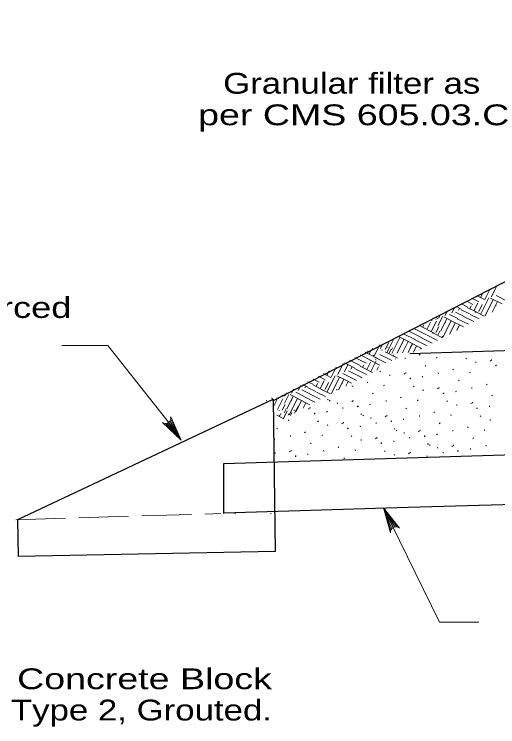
# Model space of a CAD drawing. Extents: x 1083.1 to 1117.1, y 697.4 to 741.4.
# Drawn here: x 1090.18 to 1093.81, y 702.44 to 707.78 of the extents above; entities that cross this region are included whole.
import ezdxf
from ezdxf.enums import TextEntityAlignment as Align

# ---------------------------------------------------------------- set-up
doc = ezdxf.new("R2010")
doc.units = 0
doc.header["$LTSCALE"] = 0.062
doc.linetypes.add('LONG_DASHED', pattern=[7.5, 6, -1.5])
doc.layers.add('1', color=7, linetype='Continuous', lineweight=13)

msp = doc.modelspace()

# ---------------------------------------------------------------- linework, layer by layer
at = {"layer": '1', "lineweight": 25}
for p, q in [((1097.77125, 707.78017), (1092.11942, 704.88033)), ((1098.91383, 705.41058), (1093.14742, 705.23408)), ((1093.22625, 705.22533), (1093.22142, 705.23075)), ((1093.34717, 705.20683), (1093.35225, 705.20767)), ((1093.11025, 705.20142), (1093.1155, 705.20233)), ((1093.57275, 705.19608), (1093.56792, 705.2015)), ((1093.64, 705.17108), (1093.64517, 705.17208)), ((1093.75433, 705.17942), (1093.7495, 705.18467)), ((1093.75867, 705.18908), (1093.76383, 705.19008)), ((1092.92925, 705.09867), (1092.92442, 705.10408)), ((1093.26708, 705.14225), (1093.26225, 705.14758)), ((1093.47667, 705.11383), (1093.47183, 705.11925)), ((1093.79117, 705.14617), (1093.79633, 705.147)), ((1093.79383, 705.14817), (1093.799, 705.149)), ((1092.9965, 705.07367), (1093.00167, 705.07467)), ((1093.11083, 705.082), (1093.106, 705.08733)), ((1093.11517, 705.09167), (1093.12033, 705.09267)), ((1093.14767, 705.04883), (1093.15283, 705.04967)), ((1093.15033, 705.05075), (1093.15558, 705.05158)), ((1093.24158, 705.064), (1093.24683, 705.06483)), ((1093.36067, 705.08992), (1093.36592, 705.09083)), ((1093.59758, 705.09533), (1093.60275, 705.09617)), ((1092.71717, 704.9925), (1092.72242, 704.9935)), ((1092.83317, 705.0165), (1092.82833, 705.02192)), ((1092.95408, 704.99792), (1092.95925, 704.99883)), ((1093.17967, 704.98717), (1093.17483, 704.99258)), ((1093.5175, 705.03075), (1093.51267, 705.03608)), ((1093.72708, 705.00233), (1093.72225, 705.00775)), ((1092.59808, 704.96658), (1092.60333, 704.96742)), ((1092.874, 704.93342), (1092.86917, 704.93875)), ((1093.24692, 704.96217), (1093.25208, 704.96317)), ((1093.36133, 704.9705), (1093.35642, 704.97583)), ((1093.36558, 704.98017), (1093.37075, 704.98117)), ((1093.39808, 704.93733), (1093.40333, 704.93817)), ((1093.40075, 704.93925), (1093.406, 704.94008)), ((1093.492, 704.9525), (1093.49725, 704.95333)), ((1093.61108, 704.97842), (1093.61633, 704.97933)), ((1092.53617, 704.88983), (1092.53133, 704.89525)), ((1092.55033, 704.88033), (1092.5455, 704.88567)), ((1093.08358, 704.905), (1093.07883, 704.91042)), ((1093.2045, 704.88642), (1093.20967, 704.88733)), ((1093.76792, 704.91933), (1093.76308, 704.92458)), ((1092.39842, 704.82975), (1092.40358, 704.83075)), ((1092.60342, 704.86483), (1092.60858, 704.86583)), ((1092.71783, 704.87317), (1092.713, 704.87842)), ((1092.72217, 704.88283), (1092.72733, 704.88375)), ((1092.75458, 704.83992), (1092.75983, 704.84075)), ((1092.75725, 704.84192), (1092.7625, 704.84275)), ((1092.8485, 704.85508), (1092.85375, 704.85592)), ((1092.96758, 704.881), (1092.97283, 704.882)), ((1093.43008, 704.87567), (1093.42525, 704.88108)), ((1093.49733, 704.85067), (1093.5025, 704.85167)), ((1093.61175, 704.859), (1093.60683, 704.86433)), ((1093.616, 704.86875), (1093.62125, 704.86967)), ((1093.74242, 704.841), (1093.74767, 704.84183)), ((1092.27975, 704.81175), (1092.28492, 704.81275)), ((1092.39408, 704.82008), (1092.38925, 704.82542)), ((1092.43092, 704.78683), (1092.43608, 704.78767)), ((1092.43358, 704.78883), (1092.43883, 704.78967)), ((1092.52483, 704.802), (1092.53008, 704.80283)), ((1092.64392, 704.828), (1092.64917, 704.82892)), ((1092.78658, 704.77833), (1092.78175, 704.78375)), ((1093.1245, 704.82192), (1093.11958, 704.82725)), ((1093.334, 704.7935), (1093.32925, 704.79892)), ((1093.6485, 704.82583), (1093.65375, 704.82667)), ((1093.65117, 704.82783), (1093.65642, 704.82867)), ((1092.23733, 704.736), (1092.2425, 704.73683)), ((1092.46292, 704.72525), (1092.45808, 704.73067)), ((1092.80075, 704.76883), (1092.79592, 704.77417)), ((1092.85383, 704.75333), (1092.85908, 704.75433)), ((1092.96825, 704.76167), (1092.96342, 704.76692)), ((1092.97258, 704.77133), (1092.97775, 704.77233)), ((1093.005, 704.72842), (1093.01025, 704.72925)), ((1093.00767, 704.73042), (1093.01292, 704.73125)), ((1093.099, 704.74358), (1093.10417, 704.74442)), ((1093.218, 704.76958), (1093.22325, 704.7705)), ((1093.45492, 704.77492), (1093.46008, 704.77583)), ((1093.6805, 704.76417), (1093.67567, 704.76958)), ((1093.74775, 704.73925), (1093.75292, 704.74017)), ((1092.15725, 704.6715), (1092.15242, 704.67675)), ((1092.53017, 704.70025), (1092.53533, 704.70125)), ((1092.6445, 704.70858), (1092.63967, 704.71392)), ((1092.64883, 704.71825), (1092.654, 704.71925)), ((1092.68133, 704.67542), (1092.68658, 704.67625)), ((1092.684, 704.67733), (1092.68925, 704.67817)), ((1092.77525, 704.6905), (1092.7805, 704.69133)), ((1092.89433, 704.7165), (1092.89958, 704.71742)), ((1093.037, 704.66683), (1093.03225, 704.67225)), ((1093.37492, 704.71042), (1093.37, 704.71575)), ((1093.58442, 704.682), (1093.57967, 704.68742)), ((1091.7535, 704.41092), (1098.91383, 704.63642)), ((1092.25083, 704.61908), (1092.25608, 704.62)), ((1092.36683, 704.643), (1092.362, 704.64842)), ((1092.48775, 704.6245), (1092.49292, 704.62533)), ((1092.71333, 704.61375), (1092.7085, 704.61917)), ((1093.05117, 704.65733), (1093.04633, 704.66267)), ((1093.10433, 704.64183), (1093.1095, 704.64283)), ((1093.21867, 704.65017), (1093.21383, 704.65542)), ((1093.223, 704.65983), (1093.22817, 704.66083)), ((1093.25542, 704.61692), (1093.26067, 704.61775)), ((1093.25808, 704.61892), (1093.26333, 704.61975)), ((1093.34942, 704.63208), (1093.35458, 704.63292)), ((1093.46842, 704.65808), (1093.47367, 704.659)), ((1093.70533, 704.66342), (1093.7105, 704.66433)), ((1092.13175, 704.59317), (1092.137, 704.594)), ((1092.40775, 704.56), (1092.40283, 704.56533)), ((1092.78058, 704.58875), (1092.78575, 704.58975)), ((1092.895, 704.59708), (1092.89008, 704.60242)), ((1092.89925, 704.60675), (1092.90442, 704.60775)), ((1092.93175, 704.56392), (1092.937, 704.56475)), ((1092.93442, 704.56583), (1092.93967, 704.56667)), ((1093.02567, 704.579), (1093.03092, 704.57983)), ((1093.14475, 704.605), (1093.15, 704.60592)), ((1093.62533, 704.59892), (1093.62042, 704.60425)), ((1092.25583, 704.50942), (1092.261, 704.51033)), ((1092.61725, 704.5315), (1092.6125, 704.53692)), ((1092.73817, 704.513), (1092.74333, 704.51392)), ((1093.28742, 704.55533), (1093.28267, 704.56075)), ((1093.30158, 704.54583), (1093.29675, 704.55117)), ((1093.35475, 704.53033), (1093.35992, 704.53133)), ((1093.46908, 704.53867), (1093.46425, 704.54392)), ((1093.47342, 704.54833), (1093.47858, 704.54933)), ((1093.59975, 704.52058), (1093.605, 704.52142)), ((1093.71883, 704.54658), (1093.72408, 704.5475)), ((1092.13717, 704.49142), (1092.14225, 704.49233)), ((1092.2515, 704.49967), (1092.24667, 704.505)), ((1092.28825, 704.4665), (1092.2935, 704.46733)), ((1092.29092, 704.4685), (1092.29617, 704.46933)), ((1092.38217, 704.48167), (1092.38742, 704.4825)), ((1092.50125, 704.50758), (1092.5065, 704.5085)), ((1092.96375, 704.50225), (1092.95892, 704.50767)), ((1093.031, 704.47725), (1093.03617, 704.47825)), ((1093.14542, 704.48558), (1093.1405, 704.49092)), ((1093.14967, 704.49525), (1093.15492, 704.49625)), ((1093.27608, 704.4675), (1093.28133, 704.46833)), ((1093.39517, 704.4935), (1093.40042, 704.49442)), ((1093.50583, 704.5055), (1093.51108, 704.50633)), ((1093.5085, 704.50742), (1093.51375, 704.50825)), ((1091.7535, 704.03733), (1091.7535, 704.41092)), ((1092.65817, 704.4485), (1092.65325, 704.45383)), ((1093.13575, 704.08392), (1100.04408, 704.29175)), ((1091.7535, 704.04233), (1093.13575, 704.08392)), ((1091.83925, 704.0335), (1091.8415, 704.0385)), ((1092.107, 704.0335), (1092.10917, 704.0385))]:
    msp.add_line(p, q, dxfattribs=at)
at = {"layer": '1'}
for p, q in [((1093.78875, 705.71933), (1093.801, 705.74383)), ((1093.678, 705.65592), (1093.69467, 705.68925)), ((1093.71, 705.64083), (1093.74783, 705.71658)), ((1093.7595, 705.66083), (1093.78808, 705.71808)), ((1093.6145, 705.64808), (1093.66525, 705.62275)), ((1093.65358, 705.66808), (1093.709, 705.64042)), ((1093.6785, 705.52958), (1093.73992, 705.65292)), ((1093.713, 705.5195), (1093.77358, 705.64092)), ((1093.753, 705.65267), (1093.83925, 705.60975)), ((1093.79667, 705.67042), (1093.88808, 705.62475)), ((1093.46242, 705.54083), (1093.48192, 705.57992)), ((1093.49725, 705.58775), (1093.53367, 705.56958)), ((1093.53625, 705.60783), (1093.5775, 705.58733)), ((1093.57533, 705.62792), (1093.62133, 705.605)), ((1093.57775, 705.58183), (1093.65058, 705.5455)), ((1093.59683, 705.57233), (1093.60758, 705.59392)), ((1093.6285, 705.5565), (1093.65708, 705.61392)), ((1093.665, 705.55033), (1093.69117, 705.60275)), ((1093.76617, 705.54692), (1093.80533, 705.62533)), ((1093.79117, 705.59367), (1093.79467, 705.60075)), ((1093.36325, 705.50075), (1093.3755, 705.52525)), ((1093.41292, 705.52083), (1093.42425, 705.54342)), ((1093.42483, 705.54475), (1093.42883, 705.55267)), ((1093.44633, 705.52867), (1093.50792, 705.49792)), ((1093.49008, 705.54642), (1093.5555, 705.51375)), ((1093.512, 705.56083), (1093.51983, 705.57658)), ((1093.534, 705.56417), (1093.59492, 705.53367)), ((1093.59933, 705.5295), (1093.667, 705.49583)), ((1093.63758, 705.54833), (1093.6445, 705.54483)), ((1093.64683, 705.54542), (1093.706, 705.51592)), ((1093.68517, 705.56417), (1093.68567, 705.56392)), ((1093.30225, 705.48758), (1093.315, 705.48125)), ((1093.30742, 705.4005), (1093.34717, 705.48008)), ((1093.341, 705.5075), (1093.35842, 705.49883)), ((1093.34275, 705.491), (1093.34367, 705.49283)), ((1093.3605, 705.44708), (1093.39333, 705.51292)), ((1093.37817, 705.40333), (1093.425, 705.49717)), ((1093.39583, 705.35958), (1093.45692, 705.48183)), ((1093.40258, 705.511), (1093.45942, 705.48267)), ((1093.41133, 705.46658), (1093.41508, 705.474)), ((1093.45692, 705.48183), (1093.54992, 705.4355)), ((1093.50433, 705.49775), (1093.58892, 705.45558)), ((1093.55175, 705.51358), (1093.62792, 705.47567)), ((1093.18358, 705.42275), (1093.27392, 705.37767)), ((1093.224, 705.44742), (1093.22725, 705.44583)), ((1093.22742, 705.4405), (1093.32992, 705.38925)), ((1093.24408, 705.432), (1093.25358, 705.45108)), ((1093.26308, 705.4675), (1093.27108, 705.4635)), ((1093.27575, 705.41625), (1093.30317, 705.47108)), ((1093.34383, 705.39392), (1093.36492, 705.43617)), ((1093.44667, 705.38225), (1093.47208, 705.43317)), ((1093.47275, 705.43442), (1093.4885, 705.46608)), ((1093.50008, 705.40975), (1093.52025, 705.45033)), ((1093.1015, 705.38442), (1093.18733, 705.34167)), ((1093.14058, 705.4045), (1093.23483, 705.3575)), ((1093.27833, 705.37342), (1093.35517, 705.33517)), ((1093.31692, 705.39208), (1093.3235, 705.38883)), ((1093.32583, 705.38933), (1093.39417, 705.35525)), ((1093.35742, 705.3735), (1093.37325, 705.40517)), ((1093.3645, 705.40792), (1093.36467, 705.40792)), ((1093.38908, 705.35775), (1093.39325, 705.366)), ((1092.96425, 705.26717), (1092.99033, 705.31958)), ((1092.97767, 705.2465), (1093.0275, 705.34642)), ((1093.01233, 705.23675), (1093.07283, 705.35775)), ((1093.05317, 705.23925), (1093.1045, 705.34217)), ((1093.0625, 705.36442), (1093.13842, 705.32658)), ((1093.09033, 705.31058), (1093.09383, 705.31758)), ((1093.09392, 705.24175), (1093.13583, 705.32575)), ((1093.13583, 705.32575), (1093.23808, 705.27475)), ((1093.18333, 705.34167), (1093.27708, 705.29492)), ((1093.23075, 705.3575), (1093.31608, 705.315)), ((1092.843, 705.23192), (1092.85875, 705.26358)), ((1092.86367, 705.26167), (1092.87008, 705.27458)), ((1092.88142, 705.21792), (1092.92325, 705.30192)), ((1092.92767, 705.27342), (1092.94225, 705.30258)), ((1092.93675, 705.26517), (1092.94367, 705.26175)), ((1092.98433, 705.281), (1092.98483, 705.28083)), ((1092.99117, 705.23525), (1093.00692, 705.26692)), ((1093.01183, 705.265), (1093.01825, 705.27792)), ((1093.13467, 705.24425), (1093.15108, 705.27708)), ((1093.15175, 705.27833), (1093.1675, 705.31)), ((1093.17558, 705.24675), (1093.19925, 705.29425)), ((1093.226, 705.2685), (1093.23092, 705.27842)), ((1092.73642, 705.20583), (1092.82042, 705.164)), ((1092.77558, 705.226), (1092.86433, 705.18175)), ((1092.81458, 705.24608), (1092.884, 705.21142)), ((1092.82933, 705.25225), (1092.83025, 705.25408)), ((1092.87467, 705.21608), (1092.87875, 705.22442)), ((1092.88417, 705.211), (1092.90775, 705.19925)), ((1092.88458, 705.20917), (1092.96858, 705.16733)), ((1092.92375, 705.22933), (1093.0125, 705.18508)), ((1092.96275, 705.24942), (1093.03217, 705.21475)), ((1092.9775, 705.25558), (1092.97842, 705.25742)), ((1093.02283, 705.21942), (1093.02692, 705.22775)), ((1093.03233, 705.21433), (1093.05592, 705.20258)), ((1092.63725, 705.13667), (1092.6495, 705.16117)), ((1092.65767, 705.09825), (1092.68475, 705.15258)), ((1092.65825, 705.16575), (1092.73275, 705.12858)), ((1092.69733, 705.18575), (1092.77658, 705.14625)), ((1092.79342, 705.1325), (1092.80292, 705.1515)), ((1092.82508, 705.11675), (1092.85242, 705.17158)), ((1092.8455, 705.18908), (1092.92475, 705.14958)), ((1092.85675, 705.10092), (1092.8965, 705.18058)), ((1092.89208, 705.19142), (1092.893, 705.19333)), ((1093.04025, 705.19475), (1093.04117, 705.19667)), ((1092.5265, 705.07325), (1092.54317, 705.10658)), ((1092.5585, 705.05817), (1092.59633, 705.13392)), ((1092.608, 705.07817), (1092.63658, 705.13542)), ((1092.689, 705.1055), (1092.78417, 705.058)), ((1092.70717, 705.11825), (1092.71642, 705.13675)), ((1092.73292, 705.12325), (1092.82325, 705.07808)), ((1092.77667, 705.14092), (1092.86858, 705.09508)), ((1092.90208, 705.11242), (1092.91425, 705.13667)), ((1092.42383, 705.04525), (1092.46983, 705.02233)), ((1092.463, 705.06542), (1092.51375, 705.04008)), ((1092.50208, 705.08542), (1092.5575, 705.05775)), ((1092.527, 704.94692), (1092.58842, 705.07025)), ((1092.5615, 704.93683), (1092.62208, 705.05825)), ((1092.6015, 705.07), (1092.68775, 705.02708)), ((1092.64517, 705.08775), (1092.73658, 705.04208)), ((1092.78008, 705.058), (1092.7885, 705.05383)), ((1092.31092, 704.95817), (1092.33042, 704.99725)), ((1092.34575, 705.00508), (1092.38217, 704.98692)), ((1092.3605, 704.97817), (1092.36833, 704.99392)), ((1092.38475, 705.02517), (1092.426, 705.00467)), ((1092.42625, 704.99917), (1092.49908, 704.96283)), ((1092.44533, 704.98967), (1092.45608, 705.01125)), ((1092.477, 704.97383), (1092.50558, 705.03125)), ((1092.5135, 704.96767), (1092.53967, 705.02008)), ((1092.61467, 704.96425), (1092.65383, 705.04267)), ((1092.63967, 705.011), (1092.64317, 705.01808)), ((1092.66792, 704.99167), (1092.68517, 705.02625)), ((1092.68517, 705.02625), (1092.7105, 705.01367)), ((1092.73258, 705.04217), (1092.7495, 705.03375)), ((1092.21175, 704.91808), (1092.224, 704.94258)), ((1092.26142, 704.93817), (1092.27275, 704.96075)), ((1092.27333, 704.96208), (1092.27733, 704.97)), ((1092.29483, 704.946), (1092.35642, 704.91525)), ((1092.33858, 704.96375), (1092.404, 704.93108)), ((1092.3825, 704.9815), (1092.44342, 704.951)), ((1092.44783, 704.94683), (1092.5155, 704.91317)), ((1092.48608, 704.96567), (1092.493, 704.96217)), ((1092.49533, 704.96275), (1092.5545, 704.93325)), ((1092.53367, 704.9815), (1092.53417, 704.98125)), ((1092.11158, 704.90358), (1092.11958, 704.89958)), ((1092.12425, 704.83358), (1092.15167, 704.88842)), ((1092.15075, 704.90492), (1092.1635, 704.89858)), ((1092.15592, 704.81783), (1092.19567, 704.89742)), ((1092.1895, 704.92483), (1092.20692, 704.91617)), ((1092.19125, 704.90833), (1092.19217, 704.91017)), ((1092.209, 704.86442), (1092.24183, 704.93025)), ((1092.22667, 704.82067), (1092.2735, 704.9145)), ((1092.24433, 704.77692), (1092.30542, 704.89917)), ((1092.25108, 704.92833), (1092.30792, 704.9)), ((1092.25983, 704.88392), (1092.26358, 704.89133)), ((1092.30542, 704.89917), (1092.39842, 704.85283)), ((1092.35283, 704.91508), (1092.43742, 704.87292)), ((1092.40025, 704.93092), (1092.47642, 704.893)), ((1092.0725, 704.8835), (1092.07575, 704.88192)), ((1092.19233, 704.81125), (1092.21342, 704.8535)), ((1092.28508, 704.789), (1092.31292, 704.84483)), ((1092.29517, 704.79958), (1092.32058, 704.8505)), ((1092.32125, 704.85175), (1092.337, 704.88342)), ((1092.34858, 704.82708), (1092.36875, 704.86767)), ((1092.16542, 704.80942), (1092.172, 704.80617)), ((1092.16975, 704.76425), (1092.18058, 704.78583)), ((1092.20142, 704.74842), (1092.23, 704.80575)), ((1092.20592, 704.79083), (1092.22175, 704.8225)), ((1092.213, 704.82525), (1092.21317, 704.82525)), ((1092.23758, 704.77508), (1092.24175, 704.78333)), ((1092.25308, 704.7725), (1092.26417, 704.79458)), ((1091.35067, 704.73117), (1091.43492, 704.58683)), ((1091.35592, 704.74292), (1091.43492, 704.58683)), ((1092.15075, 704.77375), (1092.204, 704.74717)), ((1091.31608, 704.712), (1091.43492, 704.58683)), ((1091.32908, 704.71417), (1091.43492, 704.58683)), ((1091.33992, 704.71975), (1091.43492, 704.58683)), ((1093.02508, 703.933), (1092.95058, 704.07833)), ((1093.01275, 703.92325), (1092.95058, 704.07833)), ((1093.00583, 703.91233), (1092.95058, 704.07833)), ((1093.03658, 703.93692), (1092.95058, 704.07833)), ((1093.04975, 703.93717), (1092.95058, 704.07833)), ((1092.95058, 704.07833), (1093.3715, 703.22283)), ((1093.66617, 703.22283), (1093.3715, 703.22283))]:
    msp.add_line(p, q, dxfattribs=at)
at = {"layer": '1', "linetype": 'LONG_DASHED'}
msp.add_line((1090.1955, 703.99042), (1091.73225, 704.03667), dxfattribs=at)
at = {"layer": '1'}
for points in [[(1091.41483, 704.626), (1090.88575, 705.29742), (1090.53967, 705.29742)], [(1091.35592, 704.76242), (1091.43492, 704.58683), (1091.2945, 704.7185)], [(1093.003, 703.89308), (1092.95058, 704.07833), (1093.07017, 703.92758)]]:
    msp.add_lwpolyline(points, dxfattribs=at)
at = {"layer": '1', "lineweight": 25}
msp.add_lwpolyline([(1092.14025, 703.75183), (1090.215, 703.71517), (1090.20975, 703.99175), (1092.12425, 704.89392)], close=True, dxfattribs=at)
at = {"layer": '1'}
for centre, start, end in [((1091.31625, 704.75287), 237.62129, 13.44741), ((1093.0436, 703.89667), 49.20838, 185.03451)]:
    msp.add_arc(centre, 0.04075, start, end, dxfattribs=at)

# ---------------------------------------------------------------- texts
for s, width, p in [('Granular filter as', 1.25, (1092.71287, 707.18442)), ('per CMS 605.03.C', 1.35, (1092.72767, 706.948))]:
    msp.add_text(s, height=0.156, dxfattribs=dict(at, width=width)).set_placement(p, align=Align.CENTER)
for s, width, p in [('Precast reinforced', 1.3, (1088.41117, 705.50333)), ('Tied Concrete Block ', 1.35, (1089.57883, 702.71983)), ('Mat, Type 2, Grouted.', 1.25, (1089.57883, 702.48517))]:
    msp.add_text(s, height=0.156, dxfattribs=dict(at, width=width)).set_placement(p)

doc.saveas('drawing.dxf')
